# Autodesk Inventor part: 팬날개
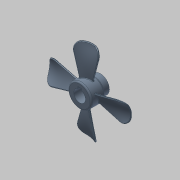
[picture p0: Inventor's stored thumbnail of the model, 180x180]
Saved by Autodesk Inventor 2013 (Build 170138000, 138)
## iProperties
Company: 한국ATC센터
Created: 2016-06
Part Number: 팬날개
Document SubType Name: Modeling
Designer: mdu
Density: 1.06 g/cm^3
Material: ABS 플라스틱
Mass: 26.2527 g
Surface Area: 149.775 cm^2
Volume: 24.7667 cm^3
Author: mdu
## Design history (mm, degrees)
sketch "스케치1"
  geometry: L1 (-15, 0)-(15, 0); L2 (-15, 0)-(-15, 17); L3 (-15, 17)-(5, 17); L4 (5, 17)-(5, 13); L5 (5, 13)-(15, 13); L6 (15, 13)-(15, 0); 2 further points
  constraints: 12 end point, 3 parallel, 2 perpendicular, 1 coincident, 1 horizontal, 1 midpoint
  dimensions: "d0" = 30 distance of L1.start L1.end; "d8" = 34 diameter of L3 L1; "d10" = 26 diameter of L5 L1; "d32" = 20 distance of L2.end L3.end
revolve "회전1" sketch "스케치1" stored, may be unused: angle "d11" = 90 deg
node "작업 평면2"
sketch "스케치7"
  geometry: L1 (-15, 17)-(5, 17) reference; L2 (-15, -17)-(5, -17) reference; L3 (-5, 17)-(-5, -17); A1 r 35 centre (-36.399, -13.457) between (-2, -7) and (-8, 7); 1 further point
  constraints: 2 end point, 2 midpoint, 2 point on circle, 1 centre point
  dimensions: "d36" = 35 radius of A1; "d37" = 10 distance from line of A1.start L2; "d38" = 10 distance from line of A1.end L1; "d45" = 3 distance from line of A1.end L3; "d46" = 3 distance from line of A1.start L3
sketch "3D 스케치1"
  geometry: L1 through (0, 0) direction (1, 0) reference; L2 through (0, 0) direction (1, 0) reference; 13 other entities
  constraints: 2 collinear
  node "투영 원본 위치 스케치7"
sketch "스케치8"
  geometry: L1 (-15, 17)-(5, 17) reference; L2 (-15, -17)-(5, -17) reference; L3 (-5, 17)-(-5, -17); A1 r 30 centre (-28.74, -3.591) between (-3, -19) and (-9, 19); 1 further point
  constraints: 2 end point, 2 midpoint, 2 point on circle, 1 centre point
  dimensions: "d43" = 30 radius of A1; "d47" = 4 distance from line of A1.end L3; "d48" = 2 distance from line of A1.start L3; "d58" = 2 distance from line of A1.end L1; "d59" = 2 distance from line of A1.start L2
sketch "3D 스케치2"
sketch "3D 스케치3"
feature "경계 패치1" sketch "3D 스케치2", "3D 스케치3" dims "d50" = 0
feature "연장1" dims "d55" = 2
feature "두껍게 하기1" dims "d51" = 2, "d52" = 2
sketch "스케치9"
  geometry: C1 r 59 at (0, 0); 1 further point
  constraints: 1 centre point, 1 coincident
  dimensions: "d60" = 118 diameter of C1
extrude "돌출2" sketch "스케치9" distance "d62" = 200; taper "d63" = 0 deg
fillet "모깎기6" dims "d64" = 10
fillet "모깎기7" dims "d66" = 0.8
fillet "모깎기8" dims "d67" = 0.8
sketch "스케치2"
  geometry: L1 (-2.5, 8.124)-(-2.5, 10.8); L2 (-2.5, 10.8)-(2.5, 10.8); L3 (2.5, 10.8)-(2.5, 8.124); A1 r 8.5 centre (0, 0) between (-2.5, 8.124) and (2.5, 8.124); 1 further point
  constraints: 6 end point, 2 parallel, 2 point on circle, 1 centre point, 1 coincident, 1 horizontal, 1 vertical
  dimensions: "d12" = 17 diameter of A1; "d13" = 5 distance of L1.end L2.end; "d14" = 19.3 dimension on A1 L2 (computed from d12)
extrude "돌출1" cut sketch "스케치2" stored distance "d15" = 10; taper "d16" = 0 deg
chamfer "모따기1" distance "d17" = 1; stored, may be unused: second distance "d18" = 2, angle "d19" = 45 deg
node "작업 평면1"
sketch "스케치3"
  geometry: L1 (5, -13)-(5, 13) reference; 3 further points
  constraints: 1 horizontal alignment, 1 midpoint
  dimensions: "d20" = 5 distance from line of L1 point (0, 0)
hole "구멍1" sketch "스케치3" at (0, 0) diameter "d21" = 3.242; stored, may be unused: countersink angle "d25" = 90 deg, drill point angle "d27" = 118 deg; dims "d22" = 6, "d23" = 4, "d24" = 2, "d26" = 8
fillet "모깎기9" dims "d77" = 2
fillet "모깎기10" dims "d78" = 2
fillet "모깎기11" dims "d79" = 2
node "솔리드1"
pattern_circular "원형 패턴1" dims "d69" = 360 deg
pattern_circular "원형 패턴2" dims angle "d72" = 360 deg
pattern_circular "원형 패턴3" dims angle "d75" = 360 deg
node "투영 원본 위치 스케치8"
node "곡면1"
node "곡면2"
node "곡면3"
node "곡면4"
feature "경계 패치2"
feature "경계 패치3"
feature "경계 패치4"
